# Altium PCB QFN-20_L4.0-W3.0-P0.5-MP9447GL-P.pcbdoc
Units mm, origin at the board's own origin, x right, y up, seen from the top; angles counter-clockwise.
Board outline 16.84 x 17.58 mm, 2 copper layers (Top Layer, Bottom Layer), stack 0 mm thick; 1 components, 0 nets, 25 pads, 0 vias.
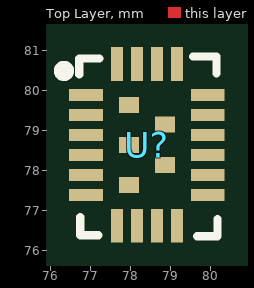
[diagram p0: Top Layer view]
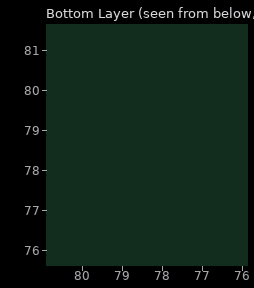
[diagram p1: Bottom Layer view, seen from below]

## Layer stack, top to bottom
Top Layer: signal copper (thickness not stored)
Bottom Layer: signal copper (thickness not stored)

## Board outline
86.685,69.85 69.85,69.85 69.85,87.426 86.685,87.426

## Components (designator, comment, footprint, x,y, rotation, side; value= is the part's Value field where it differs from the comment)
U? "" QFN-20_L4.0-W3.0-P0.5-MP9447GL-P 78.397,78.638 r0 top

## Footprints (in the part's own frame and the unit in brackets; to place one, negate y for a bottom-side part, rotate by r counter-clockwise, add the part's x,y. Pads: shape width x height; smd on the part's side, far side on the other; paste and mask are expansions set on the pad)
QFN-20_L4.0-W3.0-P0.5-MP9447GL-P [mm]
  rect 0.838x0.3 smd paste+0 mask+0.05: 1(-1.519,1.25) 2(-1.519,0.75) 3(-1.519,0.25) 4(-1.519,-0.25) 5(-1.519,-0.75) 6(-1.519,-1.25) 11(1.519,-1.25) 12(1.519,-0.75) 13(1.519,-0.25) 14(1.519,0.25) 15(1.519,0.75) 16(1.519,1.25)
  rect 0.3x0.838 smd paste+0 mask+0.05: 7(-0.75,-2.019) 8(-0.25,-2.019) 9(0.25,-2.019) 10(0.75,-2.019) 17(0.75,2.019) 18(0.25,2.019) 19(-0.25,2.019) 20(-0.75,2.019)
  rect 0.5x0.4 smd paste+0 mask+0.05: 21(-0.45,1) 22(-0.45,0) 23(-0.45,-1) 24(0.45,0.51) 25(0.45,-0.51)
  silkscreen extent -2.2,-2.29 1.77,2.21

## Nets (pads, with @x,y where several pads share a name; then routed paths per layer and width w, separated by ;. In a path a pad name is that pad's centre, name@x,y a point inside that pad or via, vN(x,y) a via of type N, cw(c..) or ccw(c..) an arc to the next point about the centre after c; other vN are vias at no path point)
pads on no net: U?.1 U?.2 U?.3 U?.4 U?.5 U?.6 U?.7 U?.8 U?.9 U?.10 U?.11 U?.12 U?.13 U?.14 U?.15 U?.16 U?.17 U?.18 U?.19 U?.20 U?.21 U?.22 U?.23 U?.24 U?.25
